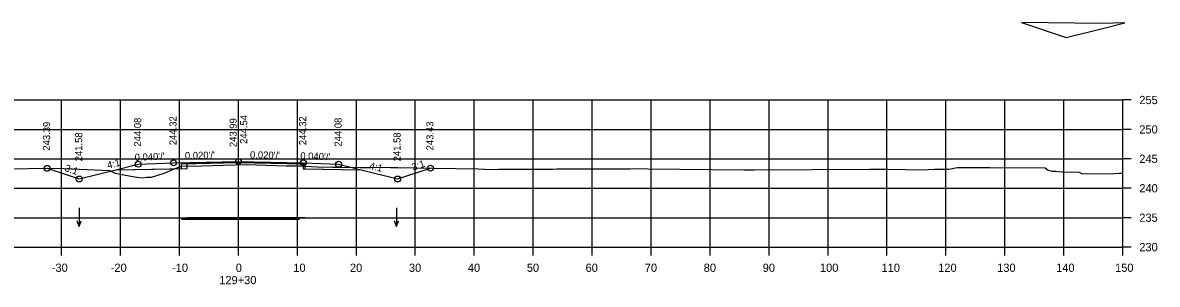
# Model space of a CAD drawing. Extents: x 1369627 to 1374022, y 380035 to 398173.
# Drawn here: x 1369747 to 1369939.4, y 382628.3 to 382672.8 of the extents above; entities that cross this region are included whole.
import ezdxf

# ---------------------------------------------------------------- set-up
doc = ezdxf.new("R2010")
doc.units = 0
for name, color, linetype in [('Default', 7, 'Continuous'), ('R_Alt Surface', 7, 'Continuous'), ('R_Axis', 7, 'Continuous'), ('R_Axis Annot', 7, 'Continuous'), ('R_Drive', 7, 'Continuous'), ('R_Exist Surface', 7, 'Continuous'), ('R_Fin Surface', 7, 'Continuous'), ('R_Grid', 7, 'Continuous'), ('R_No Plot', 7, 'Continuous'), ('R_Water Annot', 7, 'Continuous'), ('R_Xsect Elev', 7, 'Continuous'), ('R_Xsect Slope', 7, 'Continuous')]:
    doc.layers.add(name, color=color, linetype=linetype)

msp = doc.modelspace()

# ---------------------------------------------------------------- linework, layer by layer
at = {"layer": 'Default'}
for points in [[(1369773.9, 382639.36), (1369793.9, 382639.36)], [(1369774.84, 382639.64), (1369794.84, 382639.64)]]:
    msp.add_lwpolyline(points, dxfattribs=at)
at = {"layer": 'R_Alt Surface'}
for points in [[(1369762.73, 382647.74), (1369772.55, 382647.94), (1369773.9, 382647.97), (1369773.9, 382648.8), (1369783.55, 382648.99), (1369794.55, 382648.77), (1369794.55, 382647.94), (1369794.55, 382647.94), (1369804.36, 382647.74)], [(1369762.73, 382647.74), (1369774.84, 382647.98), (1369774.84, 382648.82), (1369783.55, 382648.99), (1369794.84, 382648.76), (1369794.84, 382647.93), (1369804.38, 382647.74)]]:
    msp.add_lwpolyline(points, dxfattribs=at)
at = {"layer": 'R_Axis'}
for p, q in [((1369933.55, 382634.62), (1369933.55, 382659.62)), ((1369934.95, 382659.62), (1369933.55, 382659.62)), ((1369934.95, 382654.62), (1369933.55, 382654.62)), ((1369934.95, 382649.62), (1369933.55, 382649.62)), ((1369934.95, 382644.62), (1369933.55, 382644.62)), ((1369934.95, 382639.62), (1369933.55, 382639.62)), ((1369633.55, 382634.62), (1369933.55, 382634.62)), ((1369753.55, 382633.22), (1369753.55, 382634.62)), ((1369763.55, 382633.22), (1369763.55, 382634.62)), ((1369773.55, 382633.22), (1369773.55, 382634.62)), ((1369783.55, 382633.22), (1369783.55, 382634.62)), ((1369793.55, 382633.22), (1369793.55, 382634.62)), ((1369803.55, 382633.22), (1369803.55, 382634.62)), ((1369813.55, 382633.22), (1369813.55, 382634.62)), ((1369823.55, 382633.22), (1369823.55, 382634.62)), ((1369833.55, 382633.22), (1369833.55, 382634.62)), ((1369843.55, 382633.22), (1369843.55, 382634.62)), ((1369853.55, 382633.22), (1369853.55, 382634.62)), ((1369863.55, 382633.22), (1369863.55, 382634.62)), ((1369873.55, 382633.22), (1369873.55, 382634.62)), ((1369883.55, 382633.22), (1369883.55, 382634.62)), ((1369893.55, 382633.22), (1369893.55, 382634.62)), ((1369903.55, 382633.22), (1369903.55, 382634.62)), ((1369913.55, 382633.22), (1369913.55, 382634.62)), ((1369923.55, 382633.22), (1369923.55, 382634.62)), ((1369933.55, 382633.22), (1369933.55, 382634.62)), ((1369934.95, 382634.62), (1369933.55, 382634.62))]:
    msp.add_line(p, q, dxfattribs=at)
at = {"layer": 'R_Drive'}
for p, q in [((1369929.93, 382672.59), (1369916.39, 382672.76)), ((1369933.92, 382672.75), (1369929.93, 382672.59)), ((1369930.1, 382671.79), (1369933.92, 382672.75))]:
    msp.add_line(p, q, dxfattribs=at)
msp.add_lwpolyline([(1369916.39, 382672.76), (1369923.92, 382670.25), (1369930.1, 382671.79)], dxfattribs=at)
at = {"layer": 'R_Exist Surface'}
msp.add_lwpolyline([(1369743.09, 382647.93), (1369752.69, 382648.02), (1369761.66, 382647.63), (1369762.64, 382647.21), (1369765.32, 382646.68), (1369766.29, 382646.52), (1369767.26, 382646.37), (1369768, 382646.51), (1369768.78, 382646.53), (1369770.8, 382647.13), (1369771.78, 382647.51), (1369772.56, 382647.85), (1369773.9, 382648.36), (1369777.31, 382648.46), (1369784.84, 382648.64), (1369791.64, 382648.44), (1369793.96, 382648.42), (1369796.88, 382648.27), (1369799.48, 382648.21), (1369800.08, 382648.21), (1369804.18, 382648.15), (1369806.08, 382648.15), (1369808.77, 382648.18), (1369809.34, 382648.17), (1369810.61, 382648.16), (1369816.71, 382648.04), (1369824.19, 382647.9), (1369826.35, 382647.82), (1369827.68, 382647.85), (1369829.73, 382647.85), (1369834.55, 382647.87), (1369836.88, 382647.89), (1369837.55, 382647.9), (1369849.98, 382647.95), (1369850.81, 382647.96), (1369852.99, 382647.94), (1369869.3, 382647.77), (1369871.02, 382647.77), (1369890.63, 382647.86), (1369892.51, 382647.87), (1369893.75, 382647.85), (1369899.64, 382647.78), (1369901.58, 382647.87), (1369903.52, 382647.84), (1369904.05, 382647.87), (1369905.44, 382648.16), (1369911, 382648.13), (1369920.4, 382648.08), (1369920.89, 382647.69), (1369921.57, 382647.55), (1369922.17, 382647.54), (1369922.66, 382647.49), (1369923.33, 382647.43), (1369926.13, 382647.35), (1369926.74, 382647.07), (1369932.11, 382647.14), (1369932.98, 382647.18), (1369933.55, 382647.18)], dxfattribs=at)
at = {"layer": 'R_Fin Surface'}
msp.add_lwpolyline([(1369751.11, 382648.01), (1369756.55, 382646.2), (1369762.73, 382647.74), (1369766.55, 382648.7), (1369772.55, 382648.94), (1369783.55, 382649.16), (1369794.55, 382648.94), (1369800.55, 382648.7), (1369804.36, 382647.74), (1369810.55, 382646.2), (1369816.12, 382648.05)], dxfattribs=at)
at = {"layer": 'R_Grid'}
for p, q in [((1369633.55, 382659.62), (1369933.55, 382659.62)), ((1369753.55, 382634.62), (1369753.55, 382659.62)), ((1369763.55, 382634.62), (1369763.55, 382659.62)), ((1369773.55, 382634.62), (1369773.55, 382659.62)), ((1369783.55, 382634.62), (1369783.55, 382659.62)), ((1369793.55, 382634.62), (1369793.55, 382659.62)), ((1369803.55, 382634.62), (1369803.55, 382659.62)), ((1369813.55, 382634.62), (1369813.55, 382659.62)), ((1369823.55, 382634.62), (1369823.55, 382659.62)), ((1369833.55, 382634.62), (1369833.55, 382659.62)), ((1369843.55, 382634.62), (1369843.55, 382659.62)), ((1369853.55, 382634.62), (1369853.55, 382659.62)), ((1369863.55, 382634.62), (1369863.55, 382659.62)), ((1369873.55, 382634.62), (1369873.55, 382659.62)), ((1369883.55, 382634.62), (1369883.55, 382659.62)), ((1369893.55, 382634.62), (1369893.55, 382659.62)), ((1369903.55, 382634.62), (1369903.55, 382659.62)), ((1369913.55, 382634.62), (1369913.55, 382659.62)), ((1369923.55, 382634.62), (1369923.55, 382659.62)), ((1369933.55, 382634.62), (1369933.55, 382659.62)), ((1369633.55, 382654.62), (1369933.55, 382654.62)), ((1369633.55, 382649.62), (1369933.55, 382649.62)), ((1369633.55, 382644.62), (1369933.55, 382644.62)), ((1369633.55, 382639.62), (1369933.55, 382639.62)), ((1369633.55, 382634.62), (1369933.55, 382634.62))]:
    msp.add_line(p, q, dxfattribs=at)
at = {"layer": 'R_No Plot'}
for centre in [(1369751.11, 382648.01), (1369766.55, 382648.7), (1369772.55, 382648.94), (1369783.55, 382649.16), (1369794.55, 382648.94), (1369800.55, 382648.7), (1369816.12, 382648.05), (1369756.55, 382646.2), (1369810.55, 382646.2)]:
    msp.add_circle(centre, 0.5, dxfattribs=at)
at = {"layer": 'R_Water Annot'}
for p, q in [((1369756.52, 382641.29), (1369756.52, 382638.15)), ((1369810.37, 382641.29), (1369810.37, 382638.15)), ((1369756.52, 382638.15), (1369756.17, 382639.11)), ((1369756.52, 382638.15), (1369756.87, 382639.11)), ((1369810.37, 382638.15), (1369810.02, 382639.11)), ((1369810.37, 382638.15), (1369810.72, 382639.11))]:
    msp.add_line(p, q, dxfattribs=at)
at = {"layer": 'R_Xsect Elev'}
msp.add_line((1369783.55, 382648.61), (1369783.55, 382658.61), dxfattribs=at)

# ---------------------------------------------------------------- texts
at = {"layer": 'R_Axis Annot'}
for s, p in [('255', (1369936.35, 382658.92)), ('250', (1369936.35, 382653.92)), ('245', (1369936.35, 382648.92)), ('240', (1369936.35, 382643.92)), ('235', (1369936.35, 382638.92)), ('230', (1369936.35, 382633.92)), ('-30', (1369751.89, 382630.42)), ('-20', (1369761.89, 382630.42)), ('-10', (1369772.29, 382630.42)), ('0', (1369783.1, 382630.42)), ('10', (1369792.86, 382630.42)), ('20', (1369802.47, 382630.42)), ('30', (1369812.47, 382630.42)), ('40', (1369822.47, 382630.42)), ('50', (1369832.47, 382630.42)), ('60', (1369842.43, 382630.42)), ('70', (1369852.47, 382630.42)), ('80', (1369862.47, 382630.42)), ('90', (1369872.47, 382630.42)), ('100', (1369882.18, 382630.42)), ('110', (1369892.63, 382630.42)), ('120', (1369902.24, 382630.42)), ('130', (1369912.24, 382630.42)), ('140', (1369922.24, 382630.42)), ('150', (1369932.24, 382630.42)), ('129+30', (1369780.3, 382628.32))]:
    msp.add_text(s, height=1.4, dxfattribs=at).set_placement(p)
at = {"layer": 'R_Xsect Elev'}
for s, p in [('243.39', (1369751.61, 382651.01)), ('244.08', (1369767.05, 382651.7)), ('244.32', (1369773.05, 382651.94)), ('243.99', (1369783.25, 382651.61)), ('244.54', (1369785.04, 382652.16)), ('244.32', (1369795.05, 382651.94)), ('244.08', (1369801.05, 382651.7)), ('243.43', (1369816.62, 382651.05)), ('241.58', (1369757.05, 382649.2)), ('241.58', (1369811.05, 382649.2))]:
    msp.add_text(s, height=1.2, rotation=90, dxfattribs=at).set_placement(p)
at = {"layer": 'R_Xsect Slope'}
for s, rotation, p in [("0.040'/'", 2.2906, (1369765.97, 382649.27)), ("0.020'/'", 1.1458, (1369774.48, 382649.57)), ("0.020'/'", 358.8542, (1369785.5, 382649.72)), ("0.040'/'", 357.7094, (1369794.02, 382649.56)), ('3:1', 341.5651, (1369753.99, 382647.58)), ('4:1', 14.0362, (1369761.43, 382647.93)), ('4:1', 345.9638, (1369805.67, 382647.93)), ('3:1', 18.4349, (1369813.18, 382647.6))]:
    msp.add_text(s, height=1.2, rotation=rotation, dxfattribs=at).set_placement(p)

doc.saveas('drawing.dxf')
